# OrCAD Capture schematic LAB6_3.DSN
size A
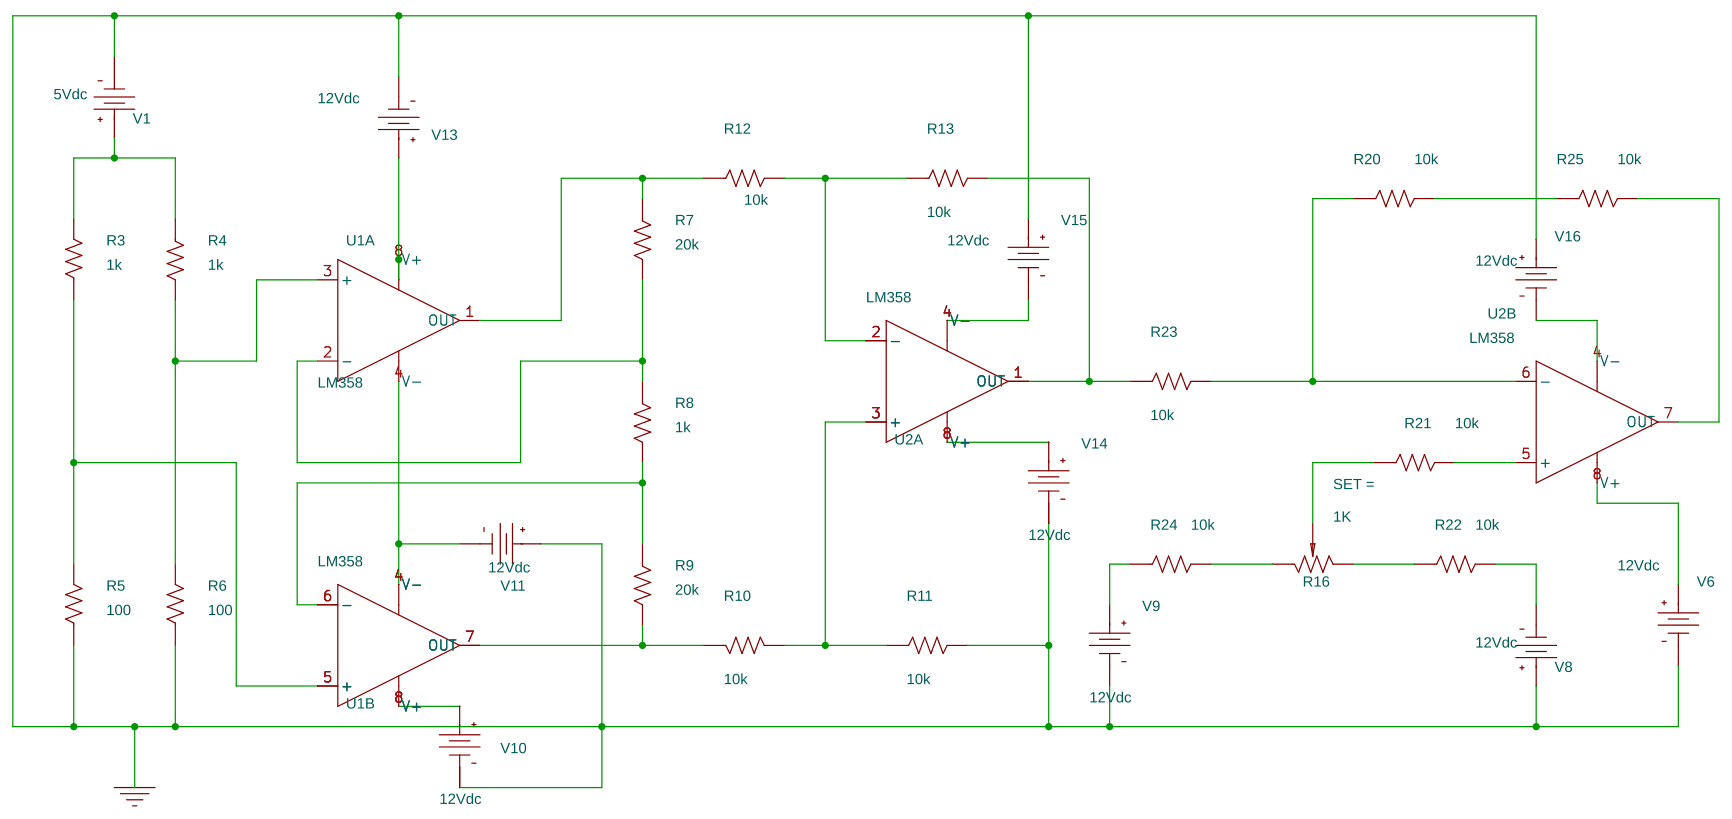
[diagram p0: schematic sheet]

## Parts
R3  1k  [AXRC05]
R4  1k  [AXRC05]
R5  100  [AXRC05]
R6  100  [AXRC05]
R7  20k  [AXRC05]
R8  1k  [AXRC05]
R9  20k  [AXRC05]
R10  10k  [AXRC05]
R11  10k  [AXRC05]
R12  10k  [AXRC05]
R13  10k  [AXRC05]
R16  1K  [VRES10]
R20  10k  [AXRC05]
R21  10k  [AXRC05]
R22  10k  [AXRC05]
R23  10k  [AXRC05]
R24  10k  [AXRC05]
R25  10k  [AXRC05]
U1  LM358  [DIP1008W300L450]  (sections A,B)
U2  LM358  [DIP1008W300L450]  (sections A,B)
V1  VDC
V6  VDC
V8  VDC
V9  VDC
V10  VDC
V11  VDC
V13  VDC
V14  VDC
V15  VDC
V16  VDC

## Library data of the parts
R3-R13 R20-R25 = R
R16 = POT
U1 U2 = LM358
V1 = VDC: DC: 5Vdc
V6 V8-V11 V13-V16 = VDC: DC: 12Vdc

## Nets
0: R5.1 R6.1 R11.2 V1.1(-) V6.1(-) V8.0(+) V9.1(-) V10.1(-) V11.0(+) V13.1(-) V14.1(-) V15.0(+) V16.0(+)
N02941: R3.2 R4.1 V1.0(+)
N03091: R3.1 R5.2 U1.5(+)
N03095: R4.2 R6.2 U1.3(+)
N05051: R7.2 R8.1 U1.2(-)
N05055: R8.2 R9.1 U1.6(-)
N05059: R9.2 R10.1 U1.7(OUT)
N05118: R7.1 R12.1 U1.1(OUT)
N05199: R10.2 R11.1 U2.3(+)
N05264: R12.2 R13.1 U2.2(-)
N06142: R13.2 R23.1 U2.1(OUT)
N06463: R20.2 R25.1
N06467: R25.2 U2.7(OUT)
N06533: R20.1 R23.2 U2.6(-)
N06561: R16.2(t) R21.1
N06569: R21.2 U2.5(+)
N06573: U2.8(V+) V6.0(+) V14.0(+)
N06631: R16.1 R24.2
N06635: R16.3(2) R22.1
N06639: R22.2 V8.1(-)
N07326: R24.1 V9.0(+)
N07505: U1.8(V+) V10.0(+) V13.0(+)
N07801: U2.4(V-) V15.1(-) V16.1(-)
N08777: U1.4(V-) V11.1(-)
